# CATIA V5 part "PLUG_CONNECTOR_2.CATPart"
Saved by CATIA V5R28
Part number: PLUG_CONNECTOR_2
Revision: ---
Publications: "MasterKeywayAxis", "InsertFrontFace", "InsertRearFace", "Logical Termination.1", "Logical Pin.1", "CCP", "Face_generated(CCP)", "Face_generated(CCP).1", "BCP", "BCPRPoint_generated(BCP)", "BCPPlane_generated(BCP)", "BaCP", "Face_generated(BaCP)", "Face_generated(BaCP).1", "CaCP", "Face_generated(CaCP)", "Axis_generated(CaCP)", "Face_generated(CaCP).1", "Axis_generated(BaCP)", "Axis_generated(CCP)"
Bounding box of the stored display mesh (mm): x 0 to 36.297, y -17.208 to 17.208, z -17.145 to 17.145
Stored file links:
  C:\Users\ajc8720\Documents\BOEING_WORK\0001-2CES\004-AP242\Boeing-Generic_Harness_R3\PLUG_CONNECTOR_2.CATPart
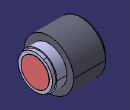
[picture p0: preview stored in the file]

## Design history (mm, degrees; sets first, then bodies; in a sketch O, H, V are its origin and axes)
Parameters
  PartNumber = "PLUG_CONNECTOR_2"
AxisSystem1 "MasterKeywayAxis": origin (0, 0, 0), X (1, 0, 0), Y (0, 1, 0), Z (0, 0, 1)
Set1 "EGF"
  Set2 "CCP"
    Point1 "CCPRPoint": (14.0208 {= deleted_ShoulderFront}, 0, 0)
    Plane1 "CCPCPlane": type OffsetPt, RefPlane yz-plane, RefPoint Point1
  Set3 "BaCP"
    Point2 "BaCPRPoint": (36.0934 {= deleted_ShellLength}, 0, 0)
    Plane2 "BaCPCPlane": type OffsetPt, RefPlane yz-plane, RefPoint Point2
  Set4 "BCP"
    Plane3 "BCPPlane": type Offset, RefPlane face of Pad6, Offset 0, reversed
    Point3 "BCPRPoint": type OnPlane, Support Plane3, H 0, V 0, Direction (0, 1, 0)
  Set5 "CaCP"
    Point4 "CaCPRPoint": (14.0208 {= deleted_ShoulderFront}, 0, 0)
    Plane4 "CaCPCPlane": type OffsetPt, RefPlane yz-plane, RefPoint Point4
Body1 "CouplingRing" (main body)
  Sketch1 on yz-plane, origin (0, 0, 0), H (0, 1, 0), V (0, 0, 1)
    circle A1 centre (0, 0) radius 17.2085
    radius A1 = 17.2085
  Pad1 "CouplingRing": profile Sketch1, direction (1, 0, 0), length 26.7716 {= deleted_CouplingRingFront + deleted_CouplingRingLength}, opposite side length -2.54 {= -( deleted_CouplingRingFront )}
  Sketch2 on zx-plane, origin (0, 0, 0), H (-1, 0, 0), V (0, 0, 1)
    line L1 (-4.5212, 17.2085) -> (-2.54, 17.2085)
    line L2 (-2.54, 17.2085) -> (-2.54, 15.3162)
    line L3 (-2.54, 15.3162) -> (-4.5212, 15.3162)
    line L4 (-4.5212, 15.3162) -> (-4.5212, 17.2085)
    distance L2 V = 2.54
    distance L4 L2 = 1.9812
    distance L3 H = 15.3162
    distance L1 L3 = 1.8923
    horizontal: L1 H, L3 H
    vertical: L2 V, L4 V
  Groove1 "CouplingRingRelief": profile Sketch2, axis Sketch2.H, angle 360
  Sketch3 on face of Pad1, origin (2.54, 0, 0), H (0, -1, 0), V (0, 0, 1)
    point P1 (0, 0)
    reference intersected line E1 through (0, 0) direction (-1, 0) from xy-plane
    reference intersected line E2 through (0, 0) direction (0, -1) from zx-plane
    coincidence: P1 E1, P1 E2
  Hole1 "CouplingRingID": placed by Sketch3, at (2.54, 0, 0) direction (1, 0, 0), diameter 27.5336 {= deleted_CouplingRingFrontID}, depth 22.0472 {= deleted_CouplingRingThreadLength}, counterbore diameter 27.5336 {= deleted_CouplingRingFrontID}, counterbore depth 1.9812 {= deleted_CouplingRingFrontIDLength}
  Sketch4 on face of Hole1, origin (24.5872, 0, 0), H (0, 1, 0), V (0, 0, -1)
    point P1 (0, 0)
    reference intersected line E1 through (0, 0) direction (0, 1) from zx-plane
    reference intersected line E2 through (0, 0) direction (1, 0) from xy-plane
    coincidence: P1 E1, P1 E2
  Hole2 "CouplingRingThruHole": placed by Sketch4, at (24.5872, 0, 0) direction (1, 0, 0), diameter 25.4 {= deleted_CouplingRingThruDia}, through (limit type 6)
Body2 "Shell"
  Sketch5 on yz-plane, origin (0, 0, 0), H (0, 1, 0), V (0, 0, 1)
    circle A1 centre (0, 0) radius 11.3284
    radius A1 = 11.3284
  Pad2 "ShellFront": profile Sketch5, direction (1, 0, 0), length 14.0208 {= deleted_ShoulderFront}
  Sketch6 on yz-plane, origin (0, 0, 0), H (0, 1, 0), V (0, 0, 1)
    circle A1 centre (0, 0) radius 12.7
    radius A1 = 12.7
  Pad3 "ShellBack": profile Sketch6, direction (1, 0, 0), length 36.0934 {= deleted_ShellLength}, opposite side length -14.0208 {= -( deleted_ShoulderFront )}
  Sketch7 on zx-plane, origin (0, 0, 0), H (-1, 0, 0), V (0, 0, 1)
    line L1 (-36.0934, 12.7) -> (-28.321, 12.7)
    line L2 (-33.7312, 12.7) -> (-33.7312, 11.8999)
    line L3 (-33.7312, 11.8999) -> (-36.0934, 11.8999)
    line L4 (-36.0934, 11.8999) -> (-36.0934, 12.7)
    line L5 (-28.321, 12.7) -> (-28.321, 12.7)
    line L6 (-28.321, 12.7) -> (-33.7312, 12.7)
    point P4 (-28.321, 12.7)
    distance P4 V = 28.321
    distance L2 V = 33.7312
    distance V L4 = 36.0934
    distance L6 H = 12.7
    distance L3 H = 11.8999
    distance L1 L3 = 0.8001
    horizontal: L1 H, L3 H, L6 H
    vertical: L2 V, L4 V, L5 V
  Groove2 "AccyTeethThread": profile Sketch7, axis Sketch7.H, angle 360
  Sketch8 on yz-plane, origin (0, 0, 0), H (0, 1, 0), V (0, 0, 1)
    point P1 (-1.4605, 0)
    line L1 (-1.4605, 0) -> (1.4605, 0)
    line L2 (1.4605, 0) -> (1.4605, 11.8872)
    line L3 (1.4605, 11.8872) -> (-1.4605, 11.8872)
    line L4 (-1.4605, 11.8872) -> (-1.4605, 0)
    distance L4 V = 1.4605
    distance H L3 = 11.8872
    coincidence: P1 H
    horizontal: L1 H, L3 H
    vertical: L2 V, L4 V
    symmetry: L2 L4 V
  Pad4 "MasterKeyway": profile Sketch8, direction (1, 0, 0), length 14.0208 {= deleted_ShoulderFront}, opposite side length -4.572 {= - ( deleted_MasterKeyFront )}
  Sketch9 on face of Pad2, origin (0, 0, 0), H (0, -1, 0), V (0, 0, 1)
    point P1 (0, 0)
    reference intersected line E1 through (0, 0) direction (0, -1) from zx-plane
    reference intersected line E2 through (0, 0) direction (-1, 0) from xy-plane
    coincidence: P1 E1, P1 E2
  Hole3 "FrontShellID": placed by Sketch9, at (0, 0, 0) direction (1, 0, 0), diameter 20.1676 {= deleted_ShellFrontID}, depth 26.7716 {= deleted_ShellLength - deleted_ShellRearIDLength}
  Sketch10 on face of Pad3, origin (36.0934, 0, 0), H (0, 1, 0), V (0, 0, 1)
    point P1 (0, 0)
    reference intersected line E1 through (0, 0) direction (0, 1) from zx-plane
    reference intersected line E2 through (0, 0) direction (-1, 0) from xy-plane
    coincidence: P1 E1, P1 E2
  Hole4 "RearShellID": placed by Sketch10, at (36.0934, 0, 0) direction (-1, 0, 0), diameter 19.5326 {= deleted_ShellRearID}, depth 9.3218 {= deleted_ShellRearIDLength}
Body3 "Insert"
  Sketch11 on yz-plane, origin (0, 0, 0), H (0, 1, 0), V (0, 0, 1)
    circle A1 centre (0, 0) radius 9.7282
    radius A1 = 9.7282
  Pad5 "InsertOD": profile Sketch11, direction (1, 0, 0), length 23.5966 {= deleted_InsertFront + deleted_InsertLength - deleted_GrommetLength}, opposite side length -2.54 {= -( deleted_InsertFront )}
  Sketch12 on yz-plane, origin (0, 0, 0), H (0, 1, 0), V (0, 0, 1)
    circle A1 centre (0, 0) radius 9.7663
    radius A1 = 9.7663
  Pad6 "GrommetOD": profile Sketch12, direction (1, 0, 0), length 36.2966 {= deleted_InsertFront + deleted_InsertLength}, opposite side length -23.5966 {= -( deleted_InsertFront + deleted_InsertLength - deleted_GrommetLength )}
Body4 "CCP"
  Sketch13 on face of Pad3, origin (14.0208, 0, 0), H (0, 1, 0), V (0, 0, 1)
    arc A1 centre (0, 0) radius 1.016 from (-0.672, 0.762) to (0.672, 0.762) ccw
    line L1 (-0.672, 0.762) -> (0.672, 0.762)
    distance L1 H = 0.762
    radius A1 = 1.016
  Pad7: profile Sketch13, direction (1, 0, 0), length 0.508
Body5 "CaCP"
  Sketch14 "Sketch" on start face of Pad3, origin (14.0208, 0, 0), H (0, 1, 0), V (0, 0, 1)
    line L1 (-0.672, 0.762) -> (0.672, 0.762)
    point P1 (-0.672, 0.762)
    point P2 (0.672, 0.762)
    arc A1 centre (0, 0) radius 1.016 from (-1.016, 0) to (1.016, 0) ccw
    point P3 (0, 0)
    point P4 (-1.016, 0)
    point P5 (1.016, 0)
    reference projected point E1 (0, 0) from Point4
    arc A2 centre (0, 0) radius 1.016 from (1.016, 0) to (0.672, 0.762) ccw
    point P6 (0, 0)
    point P7 (1.016, 0)
    point P8 (0.672, 0.762)
    arc A3 centre (0, 0) radius 1.016 from (-0.672, 0.762) to (-1.016, 0) ccw
    point P9 (0, 0)
    point P10 (-0.672, 0.762)
    point P11 (-1.016, 0)
    reference projected point E2 (0, 0) from Point4
    reference projected point E3 (0, 0) from Point4
    length L1 = 1.344
    radius A1 = 1.016
    radius A3 = 1.016
    radius A2 = 1.016
    distance L1 P5 = 0.762
    distance P4 L1 = 0.762
    distance P7 L1 = 0.762
    distance P11 L1 = 0.762
    coincidence: P3 E1, P6 E2, P9 E3, P8 P2, P10 P1
    horizontal: L1 H
  Pad8: profile Sketch14, direction (1, 0, 0), length 0.508, opposite side up to start face of Pad3
Body6 "BaCP"
  Sketch15 on face of Pad3, origin (36.0934, 0, 0), H (0, 1, 0), V (0, 0, 1)
    arc A1 centre (0, 0) radius 1.016 from (-0.672, 0.762) to (0.672, 0.762) ccw
    line L1 (-0.672, 0.762) -> (0.672, 0.762)
    distance L1 H = 0.762
    radius A1 = 1.016
  Sketch16 on face of Pad3, origin (36.0934, 0, 0), H (0, 1, 0), V (0, 0, 1)
    circle A1 centre (0, 0) radius 1.27
    radius A1 = 1.27
  Pad9: profile Sketch16, direction (1, 0, 0), length 0.254, opposite side length 0.254
  Pocket1: profile Sketch15, direction (1, 0, 0), through (limit type 6)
